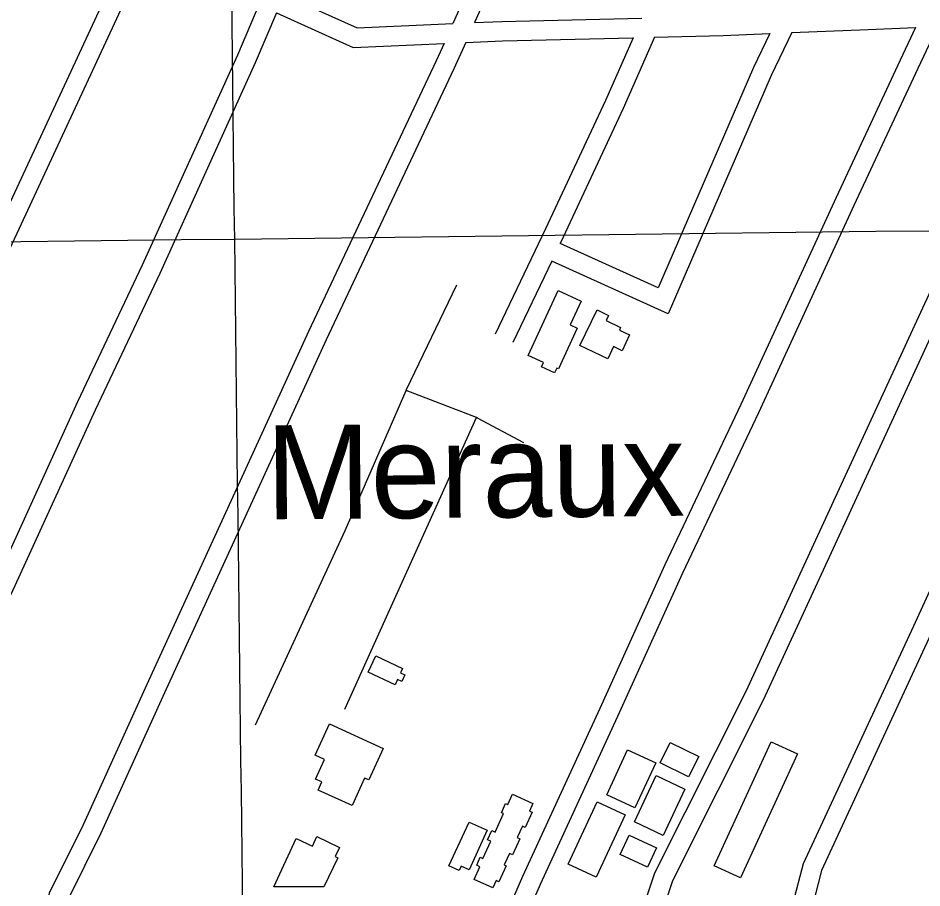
# Model space of a CAD drawing. Extents: x 3704301 to 3742427, y 506229 to 532009.
# Drawn here: x 3718650 to 3720045, y 522892 to 524234 of the extents above; entities that cross this region are included whole.
import ezdxf

# ---------------------------------------------------------------- set-up
doc = ezdxf.new("R2010")
doc.units = 0
for name, color, linetype in [('V-BLDG-OTLN', 7, 'Continuous'), ('V-GRID-MAJR', 7, 'Continuous'), ('V-ROAD-CNTR', 7, 'Continuous'), ('V-TOPO-GNAM-IDEN', 7, 'Continuous'), ('V-TOPO-SHOR', 7, 'Continuous')]:
    doc.layers.add(name, color=color, linetype=linetype)

msp = doc.modelspace()

# ---------------------------------------------------------------- linework, layer by layer
at = {"layer": 'V-BLDG-OTLN'}
for points in [[(3719437.592, 523713.365), (3719483.7460000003, 523813.5), (3719519.197, 523797.163), (3719502.4050000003, 523760.727), (3719513.325, 523755.691), (3719484.286, 523692.69200000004), (3719481.575, 523693.94200000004), (3719478.273, 523686.782), (3719458.25, 523696.01), (3719461.228, 523702.47000000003)], [(3719517.509, 523728.944), (3719543.807, 523783.704), (3719561.625, 523775.147), (3719557.947, 523767.49), (3719580.204, 523756.795), (3719578.269, 523752.75800000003), (3719594.096, 523745.15400000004), (3719582.427, 523720.854), (3719569.477, 523727.074), (3719560.466, 523708.315)], [(3719202.162, 523249.757), (3719243.734, 523230.483), (3719240.642, 523223.815), (3719247.37, 523220.696), (3719242.649, 523210.515), (3719236.057, 523213.569), (3719232.221, 523205.299), (3719190.515, 523224.63800000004)], [(3719130.728, 523144.777), (3719213.877, 523106.772), (3719191.7320000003, 523058.322), (3719185.131, 523061.33900000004), (3719165.7260000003, 523018.886), (3719113.291, 523042.854), (3719118.948, 523055.226), (3719109.117, 523059.719), (3719122.935, 523089.954), (3719108.6550000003, 523096.485)], [(3719656.894, 523116.12700000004), (3719700.705, 523094.463), (3719685.183, 523063.072), (3719641.37, 523084.738)], [(3719853.014, 523098.643), (3719765.147, 522907.221), (3719724.863, 522925.71400000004), (3719812.73, 523117.13300000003)], [(3719634.487, 523084.738), (3719602.237, 523015.14900000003), (3719558.772, 523035.293), (3719591.032, 523104.873)], [(3719679.485, 523044.009), (3719645.769, 522972.798), (3719601.426, 522993.792), (3719635.144, 523065.003)], [(3719386.572, 522977.799), (3719399.5500000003, 523006.36100000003), (3719396.2290000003, 523007.87200000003), (3719402.71, 523022.136), (3719406.0160000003, 523020.63300000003), (3719413.268, 523036.591), (3719444.793, 523022.267), (3719439.415, 523010.43200000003), (3719443.603, 523008.527), (3719432.927, 522985.037), (3719428.6380000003, 522986.984), (3719420.7, 522969.51300000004), (3719424.722, 522967.684), (3719413.43, 522942.83400000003), (3719408.77, 522944.951), (3719400.6890000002, 522927.173), (3719403.573, 522925.864), (3719392.305, 522901.07300000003), (3719387.9790000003, 522903.039), (3719382.882, 522891.818), (3719354.126, 522904.884), (3719362.985, 522924.37700000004), (3719358.023, 522926.634), (3719363.659, 522939.03500000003), (3719367.565, 522937.259), (3719379.685, 522963.93), (3719374.884, 522966.11100000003), (3719381.288, 522980.201)], [(3719587.0670000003, 523004.401), (3719542.4050000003, 522908.423), (3719499.208, 522928.52400000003), (3719543.881, 523024.496)], [(3719315.275, 522925.647), (3719346.417, 522993.429), (3719374.2600000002, 522980.64), (3719346.327, 522919.841), (3719334.162, 522925.43), (3719330.953, 522918.444)], [(3719044.833, 522893.24700000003), (3719079.491, 522968.077), (3719104.421, 522956.42), (3719111.237, 522970.998), (3719146.393, 522954.04000000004), (3719139.598, 522940.085), (3719143.753, 522938.054), (3719121.989, 522893.424)], [(3719593.308, 522973.298), (3719635.605, 522953.835), (3719621.7090000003, 522923.63800000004), (3719579.414, 522943.102)]]:
    msp.add_lwpolyline(points, close=True, dxfattribs=at)
at = {"layer": 'V-GRID-MAJR'}
for points in [[(3719130.791, 511775.213), (3719057.661, 517832.646), (3718984.494, 523893.163), (3718911.326, 529953.694), (3718911.289, 529956.764)], [(3708427.129, 523767.243), (3713705.816, 523829.819), (3718984.494, 523893.163), (3724263.162, 523957.275), (3729541.821, 524022.155), (3734820.471, 524087.803), (3740099.111, 524154.218), (3740099.112, 524154.218)]]:
    msp.add_spline(points, degree=3, dxfattribs=at)
at = {"layer": 'V-ROAD-CNTR'}
for points in [[(3719877.906205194, 525446.098081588), (3719867.0242269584, 525403.0681676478), (3719717.04852691, 525086.6268005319), (3719575.9248091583, 524783.139407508), (3719432.990095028, 524474.331025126), (3719321.3563182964, 524225.63752251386)], [(3719906.9901470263, 525438.7420962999), (3719895.3901702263, 525392.8701880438), (3719744.204472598, 525073.876826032), (3719603.13875473, 524770.51343276), (3719460.288040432, 524461.887050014), (3719354.89425122, 524227.0965195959)], [(3718819.4513221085, 524345.6452824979), (3718797.968365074, 524295.4013829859), (3718620.919719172, 523914.3191451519), (3718481.788997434, 523618.77973623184), (3718354.6652516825, 523341.36329106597), (3718195.6335697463, 522992.82598814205), (3718150.650659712, 522891.81019017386), (3718125.6327097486, 522817.055339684)], [(3718846.8122673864, 524333.328307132), (3718825.37031027, 524283.1814074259), (3718648.09566482, 523901.60917057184), (3718508.996943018, 523606.141761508), (3718381.949197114, 523328.8873160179), (3718222.983515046, 522980.49801279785), (3718178.6426037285, 522880.92221194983), (3718154.082652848, 522807.5353587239)], [(3719061.0588388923, 524269.78043422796), (3719173.4046142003, 524219.20653537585), (3719321.3553182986, 524225.63752251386)], [(3719021.8639172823, 524254.526464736), (3718988.6439837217, 524177.15361948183), (3718841.6692776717, 523852.59226860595), (3718742.0714768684, 523641.78369022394), (3718617.712725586, 523370.4562328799), (3718499.8659612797, 523119.1157355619), (3718394.465172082, 522889.771194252), (3718378.4642040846, 522820.7793322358)], [(3719049.2238625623, 524242.21048936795), (3719016.0939288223, 524165.0476436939), (3718868.897223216, 523839.996293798), (3718769.271422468, 523629.12571553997), (3718644.9306711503, 523357.83825811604), (3718527.0779068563, 523106.4837608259), (3718422.999115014, 522880.01921375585), (3718407.688145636, 522814.00134579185)], [(3719049.222862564, 524242.2094893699), (3719167.588625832, 524188.92459593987), (3719307.6083457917, 524195.01158376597)], [(3719354.893251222, 524227.095519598), (3719396.877167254, 524228.9205159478), (3719612.8267353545, 524234.13950550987)], [(3720251.1234587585, 524227.2095193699), (3720049.354862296, 523793.38738701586), (3719877.9532051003, 523421.47613083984), (3719773.2974144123, 523194.75158429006), (3719632.7606954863, 522914.50214478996), (3719615.159730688, 522862.20924937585)], [(3720284.663391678, 524228.18651741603), (3720076.578807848, 523780.7834122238), (3719905.195150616, 523408.91215596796), (3719800.331360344, 523181.73761031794), (3719660.5206399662, 522902.93616792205), (3719643.5916738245, 522852.63926851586)], [(3720464.268032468, 524233.0105077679), (3720449.198062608, 524198.6415765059), (3720299.64736171, 523870.883232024), (3720191.3345783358, 523642.9176879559), (3720032.0348969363, 523295.8133821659), (3719862.117236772, 522928.7551162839), (3719846.154268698, 522868.0992375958)], [(3720497.350966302, 524233.752506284), (3720476.5840078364, 524186.39160100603), (3720326.8433073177, 523858.2192573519), (3720218.516523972, 523630.22371334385), (3720059.2808424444, 523283.25540728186), (3719890.4551800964, 522918.5571366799), (3719875.166210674, 522860.4632528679)], [(3720035.5648898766, 524219.537534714), (3720011.751937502, 524169.252635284), (3719912.8421353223, 523957.3990589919), (3719765.66342968, 523637.6376985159), (3719648.670663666, 523390.0961935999), (3719548.056864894, 523168.65463648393), (3719428.9091031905, 522909.328155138), (3719405.9011492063, 522857.2692592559)], [(3720069.37282226, 524220.83253212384), (3720038.8998832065, 524156.48666081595), (3719940.060080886, 523944.7810842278), (3719792.851375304, 523624.9557238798), (3719675.890609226, 523377.48021883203), (3719575.342810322, 523156.18666141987), (3719456.261048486, 522897.00217979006), (3719433.341094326, 522845.1412835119)], [(3719844.4312721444, 524211.69355040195), (3719812.8323353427, 524145.60968257), (3719653.4946540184, 523777.79441820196), (3719473.96401308, 523859.1612554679)], [(3719810.4833400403, 524210.24255330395), (3719785.526389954, 524158.04765769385), (3719638.092684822, 523817.712338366), (3719486.886987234, 523886.24120130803)], [(3719632.604695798, 524204.6085645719), (3719738.717483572, 524207.1735594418), (3719810.482340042, 524210.2415533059)], [(3719844.4292721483, 524211.69355040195), (3719962.1350367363, 524216.7255403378), (3720035.5648898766, 524219.537534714)], [(3719341.1472787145, 524196.4715808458), (3719322.813315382, 524155.62666253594), (3719125.871709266, 523737.76849825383), (3719014.7969314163, 523494.993983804), (3718876.304208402, 523193.070587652), (3718777.679405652, 522976.326021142), (3718727.2795064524, 522874.31522516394), (3718719.261522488, 522826.49132081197)], [(3719341.145278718, 524196.4695808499), (3719397.891165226, 524198.93657591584), (3719599.4747620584, 524203.8085661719)], [(3719599.4747620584, 524203.80956617), (3719556.879847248, 524107.0477596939), (3719464.4990320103, 523908.9851558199), (3719386.815187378, 523746.19448140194)], [(3719632.605695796, 524204.60956456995), (3719584.205792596, 524094.66178446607), (3719491.630977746, 523896.1851814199), (3719486.885987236, 523886.24220130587)], [(3719307.60934579, 524195.01258376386), (3719295.557369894, 524168.16463746), (3719098.661763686, 523750.4044729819), (3718987.522985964, 523507.4879588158), (3718849.0162629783, 523205.53656271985), (3718750.5714598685, 522989.1859954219), (3718698.4235641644, 522883.63720651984), (3718689.673581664, 522831.4513108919)], [(3719473.96401308, 523859.162255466), (3719413.8911332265, 523733.27450724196)]]:
    msp.add_lwpolyline(points, dxfattribs=at)
at = {"layer": 'V-TOPO-SHOR'}
msp.add_line((3719154.687, 523167.49700000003), (3719357.8000000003, 523617.537), dxfattribs=at)
for points in [[(3719016.818, 523143.196), (3719154.941, 523443.205), (3719249.065, 523659.257), (3719249.794, 523660.93), (3719327.514, 523822.65400000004)], [(3719430.848, 523578.631), (3719359.4220000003, 523616.912), (3719357.8000000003, 523617.537), (3719249.065, 523659.257)]]:
    msp.add_lwpolyline(points, dxfattribs=at)

# ---------------------------------------------------------------- texts
at = {"layer": 'V-TOPO-GNAM-IDEN'}
msp.add_text('Meraux', height=144.999711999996, rotation=0.48715826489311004, dxfattribs=at).set_placement((3719033.2988944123, 523460.589052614))

doc.saveas('drawing.dxf')
